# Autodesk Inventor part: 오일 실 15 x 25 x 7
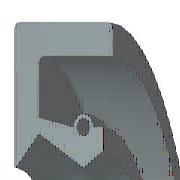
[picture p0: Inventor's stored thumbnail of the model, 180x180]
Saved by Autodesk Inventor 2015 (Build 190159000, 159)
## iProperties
Created: 2012-02
Part Number: 오일 실 15 x 25 x 7
Material: 고무
Description: 오일-실
Document SubType Name: Modeling
Standard: KS B 2804
Designer: mduedu
Standards Organization: KS
Language: ko-KR
Size Designation: D - 15 25 7
Categories: <MemberInstance><Categories><Category DisplayName="샤프트 부품" InternalName="7f7aeb1f-a693-4053-b835-cee3144e0d98" Mnemonic="SHFT"><Category DisplayName="실링" Intern
Density: 0.93 g/cm^3
Mass: 1.46464 g
Surface Area: 21.6685 cm^2
Volume: 1.57488 cm^3
Appearance: 고무 - 검은색 - 버전 1.1
IsCustomPart: 1
Author: mduedu
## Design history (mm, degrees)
revolve "본체" stored, may be unused: angle "d17" = 90 deg
revolve "스프링1" stored, may be unused: angle "d18" = 90 deg
body "Solid1"
sketch "스케치1"
  geometry: L1 (0, 12.5)-(7, 12.5); L2 (7, 10.75)-(1.75, 10.75); L3 (1.75, 9.25)-(4.9, 7.5); L4 (4.9, 7.5)-(0, 7.5); L5 (0, 0)-(9.586, 0) reference; L6 (4.9, 7.5)-(6.3, 8.375); L7 (0, 18)-(0, -3) reference; L8 (-1.941, 0)-(11.507, 0) reference; L9 (4.2, 9.6)-(1.75, 10.09); L10 (1.75, 10.09)-(1.75, 10.75); L11 (0, 12.5)-(0, 7.588); L12 (4.9, 7.5)-(0, 7.5); L13 (1.75, 9.25)-(0.152, 7.528); L14 (7, 12.5)-(7, 10.75); L15 (5.6, 9.6)-(6.3, 9.6); L16 (6.3, 9.6)-(6.3, 8.375); C1 r 0.455 at (4.9, 9.6); A1 r 0.7 centre (4.9, 9.6) between (5.6, 9.6) and (4.2, 9.6); A2 r 0.088 centre (0.088, 7.588) between (0, 7.588) and (0.152, 7.528); 1 further point
  constraints: 28 end point, 5 horizontal alignment, 5 point on line, 4 point on circle, 4 vertical alignment, 3 centre point, 3 tangent, 2 collinear, 2 horizontal, 2 perpendicular, 1 coincident, 1 parallel
  dimensions: "d0" = 25 diameter of L1 L5 (= SD2); "d1" = 1.75 distance of L1.end L2.start (= SD); "d2" = 0.91 diameter of C1 (= SPDI); "d3" = 1.4 diameter of A1 (= SPDA); "d4" = 15 diameter of L3.end L5 (= NND); "d5" = 18.5 diameter of L3.start L5 (= TKDM); "d7" = 20.18 diameter of L9.end L5 (= TKDM + 0.24 x SWDT); "d8" = 1.75 distance between parallel lines of L11 L10 (= SD); "d9" = 4.9 distance from line of L11 C1.centre (= SPDST); "d10" = 19.2 diameter of C1.centre L5 (= HLDM); "d11" = 0.0875 radius of A2 (= 0.25 x LAB); "d12" = 6.3 distance between parallel lines of L11 L16 (= SDI); "d13" = 16.75 diameter of L6.end L5 (= ABDM); "d14" = 7 distance from line of L11 L1.end (= SWDT)
fillet "모깎기1" dims "d6" = 0.3 (= RR)
other parameters: "SD2" = 25 [user parameter; used in 1 equation term], "SWDT" = 7 [user parameter; used in 2 equation terms], "RR" = 0.3 [user parameter; used in 1 equation term], "SD" = 1.75 [user parameter; used in 2 equation terms], "NND" = 15 [user parameter; used in 1 equation term], "SPDA" = 1.4 [user parameter; used in 1 equation term], "SPDI" = 0.91 [user parameter; used in 1 equation term], "TKDM" = 18.5 [user parameter; used in 2 equation terms], "HLDM" = 19.2 [user parameter; used in 1 equation term], "ABDM" = 16.75 [user parameter; used in 1 equation term], "SDI" = 6.3 [user parameter; used in 1 equation term], "SPDST" = 4.9 [user parameter; used in 1 equation term], "LAB" = 0.35 [user parameter; used in 1 equation term], "d15" = 0, "d16" = 0, "d19" = 0
